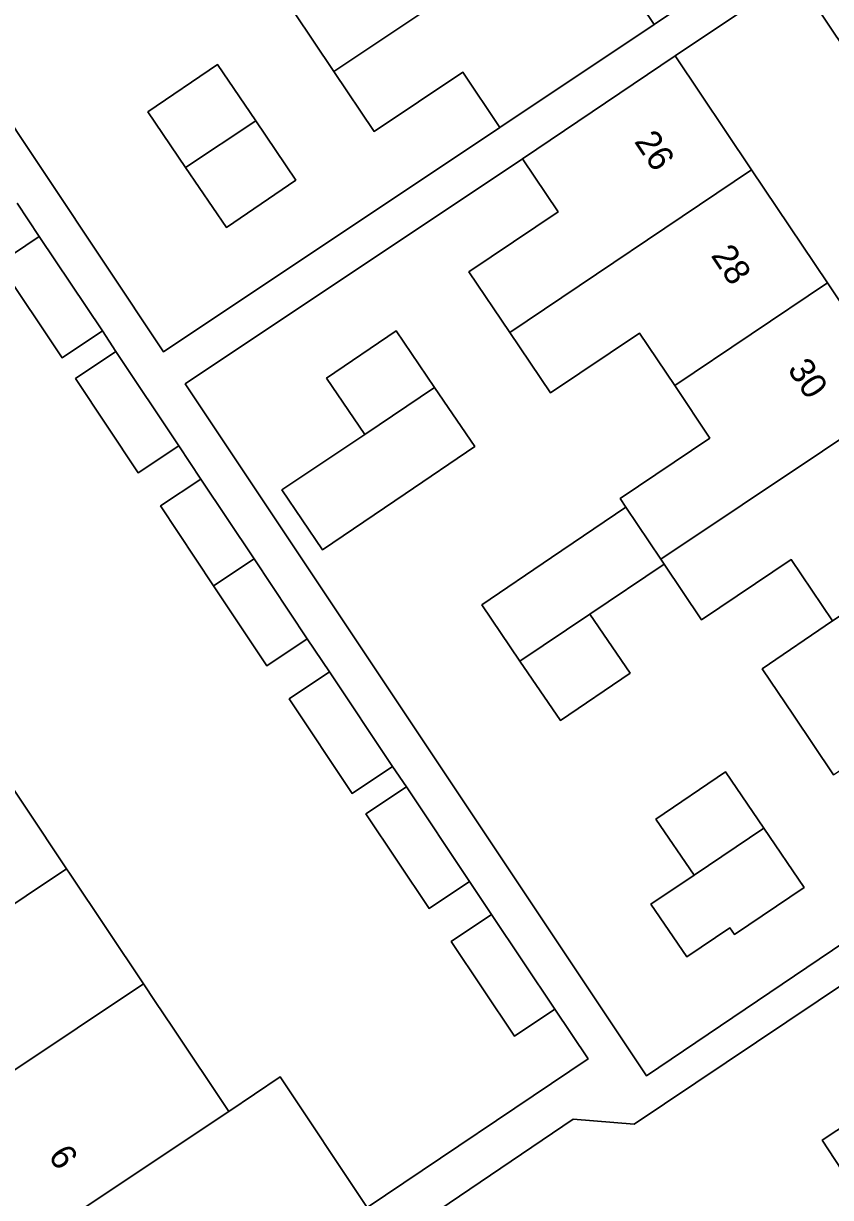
# Model space of a CAD drawing. Extents: x 158352 to 159489, y 383828 to 384603.
# Drawn here: x 158757.64 to 158789.18, y 384301.82 to 384347.71 of the extents above; entities that cross this region are included whole.
import ezdxf

# ---------------------------------------------------------------- set-up
doc = ezdxf.new("R2010")
doc.units = 0
for name, color, linetype in [('IMGEO_Erf', 7, 'Continuous'), ('IMGEO_Pand', 7, 'Continuous'), ('IMGEO_Pand_nummerreeks', 7, 'Continuous'), ('IMGEO_Voetpad_open', 7, 'Continuous')]:
    doc.layers.add(name, color=color, linetype=linetype)

msp = doc.modelspace()

# ---------------------------------------------------------------- linework, layer by layer
at = {"layer": 'IMGEO_Erf'}
for points in [[(158768.932, 384377.759), (158765.29, 384375.317), (158768.421, 384370.629), (158768.12, 384370.429), (158770.944, 384366.215), (158771.21, 384366.393), (158774.349, 384361.704), (158773.343, 384361.031), (158776.32, 384356.584), (158779.269, 384352.177), (158782.283, 384347.674), (158786.99, 384350.831)], [(158787.815, 384349.601), (158783.109, 384346.446), (158786.094, 384341.995), (158789.06, 384337.574), (158792.045, 384333.123), (158793.05, 384333.798), (158796.193, 384329.112), (158795.928, 384328.925), (158798.729, 384324.728), (158799.003, 384324.912), (158802.155, 384320.22), (158805.854, 384322.701), (158805.841, 384322.72)], [(158765.216, 384346.11), (158766.711, 384343.911), (158768.286, 384341.592), (158765.565, 384339.743), (158763.975, 384342.083), (158762.495, 384344.261)], [(158775.271, 384331.179), (158772.55, 384329.33), (158769.318, 384327.134), (158767.74, 384329.481), (158770.971, 384331.653), (158769.48, 384333.848), (158772.201, 384335.697), (158773.702, 384333.489)], [(158806.727, 384321.4), (158806.635, 384321.537), (158781.507, 384304.689), (158779.118, 384304.891), (158760.941, 384292.573), (158761.047, 384292.415), (158777.399, 384267.966), (158780.803, 384270.248), (158817.185, 384294.673), (158817.422, 384294.304), (158819.223, 384295.504), (158819, 384295.815), (158819.742, 384296.409), (158822.323, 384298.139)], [(158785.076, 384318.465), (158786.576, 384316.257), (158788.146, 384313.947), (158785.425, 384312.098), (158785.24, 384312.37), (158783.56, 384311.228), (158782.161, 384313.288), (158783.846, 384314.421), (158782.355, 384316.616)], [(158788.849, 384304.071), (158791.101, 384305.55), (158793.625, 384307.208), (158795.414, 384304.485), (158792.923, 384302.849), (158790.638, 384301.348)]]:
    msp.add_lwpolyline(points, close=True, dxfattribs=at)
for points in [[(158756.206, 384345.242), (158763.113, 384334.884), (158776.252, 384343.646), (158774.808, 384345.808), (158771.336, 384343.489), (158769.772, 384345.831), (158768.208, 384348.173), (158771.665, 384350.482), (158770.284, 384352.55), (158768.902, 384354.619), (158765.428, 384352.298), (158763.856, 384354.652), (158762.283, 384357.006), (158765.731, 384359.308), (158764.124, 384361.714), (158764.918, 384362.245), (158763.722, 384364.035), (158760.167, 384361.661), (158758.593, 384364.018), (158757.051, 384366.326), (158760.534, 384368.651), (158759.083, 384370.824), (158759.016, 384370.924), (158748.765, 384364.047)], [(158789.295, 384318.344), (158787.727, 384320.675), (158786.51, 384322.484), (158789.254, 384324.363), (158787.639, 384326.764), (158784.137, 384324.409), (158782.678, 384326.58), (158779.771, 384324.626), (158781.341, 384322.316), (158778.62, 384320.467), (158777.041, 384322.791), (158775.55, 384324.985), (158778.271, 384326.834), (158781.179, 384328.81), (158780.951, 384329.148), (158784.465, 384331.51), (158783.088, 384333.559), (158781.71, 384335.608), (158778.233, 384333.27), (158776.641, 384335.64), (158775.048, 384338.009), (158778.528, 384340.349), (158777.138, 384342.418), (158763.953, 384333.625), (158781.988, 384306.582), (158795.999, 384316.057)], [(158756.125, 384319.452), (158759.321, 384314.671), (158759.46, 384314.462), (158762.322, 384310.18), (158762.786, 384309.485), (158763.459, 384308.478), (158765.656, 384305.19), (158767.669, 384306.535), (158771.074, 384301.44), (158779.708, 384307.248), (158778.401, 384309.181), (158776.822, 384308.126), (158774.35, 384311.826), (158775.93, 384312.881), (158775.071, 384314.18), (158773.491, 384313.124), (158771.022, 384316.818), (158772.601, 384317.874), (158772.064, 384318.669), (158770.483, 384317.615), (158768.019, 384321.311), (158769.6, 384322.365), (158768.729, 384323.662), (158767.147, 384322.609), (158765.068, 384325.732), (158762.988, 384328.854), (158764.569, 384329.907), (158763.706, 384331.203), (158762.125, 384330.15), (158759.666, 384333.842), (158761.247, 384334.895), (158760.724, 384335.696), (158759.144, 384334.64), (158756.675, 384338.335), (158758.255, 384339.391), (158757.396, 384340.69)]]:
    msp.add_lwpolyline(points, dxfattribs=at)
at = {"layer": 'IMGEO_Pand'}
for points in [[(158770.284, 384352.55), (158771.665, 384350.482), (158768.208, 384348.173), (158769.772, 384345.831), (158779.269, 384352.177), (158776.32, 384356.584)], [(158779.269, 384352.177), (158769.772, 384345.831), (158771.336, 384343.489), (158774.808, 384345.808), (158776.252, 384343.646), (158782.283, 384347.674)], [(158786.094, 384341.995), (158783.109, 384346.446), (158777.138, 384342.418), (158778.528, 384340.349), (158775.048, 384338.009), (158776.641, 384335.64)], [(158763.975, 384342.083), (158766.711, 384343.911), (158765.216, 384346.11), (158762.495, 384344.261)], [(158763.975, 384342.083), (158765.565, 384339.743), (158768.286, 384341.592), (158766.711, 384343.911)], [(158789.06, 384337.574), (158786.094, 384341.995), (158776.641, 384335.64), (158778.233, 384333.27), (158781.71, 384335.608), (158783.088, 384333.559)], [(158758.255, 384339.391), (158756.675, 384338.335), (158759.144, 384334.64), (158760.724, 384335.696)], [(158792.045, 384333.123), (158789.06, 384337.574), (158783.088, 384333.559), (158784.465, 384331.51), (158780.951, 384329.148), (158781.179, 384328.81), (158782.544, 384326.779)], [(158770.971, 384331.653), (158773.702, 384333.489), (158772.201, 384335.697), (158769.48, 384333.848)], [(158761.247, 384334.895), (158759.666, 384333.842), (158762.125, 384330.15), (158763.706, 384331.203)], [(158773.702, 384333.489), (158770.971, 384331.653), (158767.74, 384329.481), (158769.318, 384327.134), (158772.55, 384329.33), (158775.271, 384331.179)], [(158795.928, 384328.925), (158796.193, 384329.112), (158793.05, 384333.798), (158792.045, 384333.123), (158782.544, 384326.779), (158782.678, 384326.58), (158784.137, 384324.409), (158787.639, 384326.764), (158789.254, 384324.363), (158790.057, 384324.903)], [(158766.649, 384326.785), (158764.569, 384329.907), (158762.988, 384328.854), (158765.068, 384325.732)], [(158782.678, 384326.58), (158782.544, 384326.779), (158781.179, 384328.81), (158778.271, 384326.834), (158775.55, 384324.985), (158777.041, 384322.791), (158779.771, 384324.626)], [(158798.729, 384324.728), (158795.928, 384328.925), (158790.057, 384324.903), (158789.254, 384324.363), (158786.51, 384322.484), (158787.727, 384320.675), (158789.295, 384318.344)], [(158766.649, 384326.785), (158765.068, 384325.732), (158767.147, 384322.609), (158768.729, 384323.662)], [(158777.041, 384322.791), (158778.62, 384320.467), (158781.341, 384322.316), (158779.771, 384324.626)], [(158772.064, 384318.669), (158769.6, 384322.365), (158768.019, 384321.311), (158770.483, 384317.615)], [(158759.321, 384314.671), (158756.125, 384319.452), (158755.986, 384319.66), (158748.172, 384314.437), (158748.31, 384314.23), (158751.501, 384309.445)], [(158783.846, 384314.421), (158786.576, 384316.257), (158785.076, 384318.465), (158782.355, 384316.616)], [(158772.601, 384317.874), (158771.022, 384316.818), (158773.491, 384313.124), (158775.071, 384314.18)], [(158786.576, 384316.257), (158783.846, 384314.421), (158782.161, 384313.288), (158783.56, 384311.228), (158785.24, 384312.37), (158785.425, 384312.098), (158788.146, 384313.947)], [(158762.322, 384310.18), (158759.46, 384314.462), (158759.321, 384314.671), (158751.501, 384309.445), (158751.64, 384309.236), (158754.497, 384304.952)], [(158775.93, 384312.881), (158774.35, 384311.826), (158776.822, 384308.126), (158778.401, 384309.181)], [(158765.656, 384305.19), (158763.459, 384308.478), (158762.786, 384309.485), (158762.322, 384310.18), (158754.497, 384304.952), (158754.961, 384304.256), (158757.826, 384299.96)], [(158765.656, 384305.19), (158757.826, 384299.96), (158758.282, 384299.276), (158761.248, 384294.829), (158769.065, 384300.088), (158771.074, 384301.44), (158767.669, 384306.535)], [(158791.101, 384305.55), (158788.849, 384304.071), (158790.638, 384301.348), (158792.923, 384302.849)]]:
    msp.add_lwpolyline(points, close=True, dxfattribs=at)
at = {"layer": 'IMGEO_Voetpad_open'}
for points in [[(158753.504, 384404.062), (158753.174, 384401.294), (158759.532, 384391.777), (158767.955, 384379.216), (158768.932, 384377.759), (158786.99, 384350.831), (158787.815, 384349.601), (158805.841, 384322.72), (158805.854, 384322.701), (158806.635, 384321.537), (158806.727, 384321.4), (158822.323, 384298.139), (158824.974, 384299.926)], [(158777.138, 384342.418), (158783.109, 384346.446), (158787.815, 384349.601), (158786.99, 384350.831), (158782.283, 384347.674), (158776.252, 384343.646), (158763.113, 384334.884), (158756.206, 384345.242)], [(158760.941, 384292.573), (158779.118, 384304.891), (158781.507, 384304.689), (158806.635, 384321.537), (158805.854, 384322.701), (158802.155, 384320.22), (158795.999, 384316.057), (158781.988, 384306.582), (158763.953, 384333.625), (158777.138, 384342.418)], [(158757.396, 384340.69), (158758.255, 384339.391), (158760.724, 384335.696), (158761.247, 384334.895), (158763.706, 384331.203), (158764.569, 384329.907), (158766.649, 384326.785), (158768.729, 384323.662), (158769.6, 384322.365), (158772.064, 384318.669), (158772.601, 384317.874), (158775.071, 384314.18), (158775.93, 384312.881), (158778.401, 384309.181), (158779.708, 384307.248), (158771.074, 384301.44)]]:
    msp.add_lwpolyline(points, dxfattribs=at)

# ---------------------------------------------------------------- texts
at = {"layer": 'IMGEO_Pand_nummerreeks'}
for s, rotation, p in [('26', 303.9102, (158781.482, 384343.1)), ('28', 303.9102, (158784.478, 384338.644)), ('30', 303.9074, (158787.471, 384334.192)), ('6', 303.7585, (158758.578, 384303.452))]:
    msp.add_text(s, height=1, rotation=rotation, dxfattribs=at).set_placement(p)

doc.saveas('drawing.dxf')
